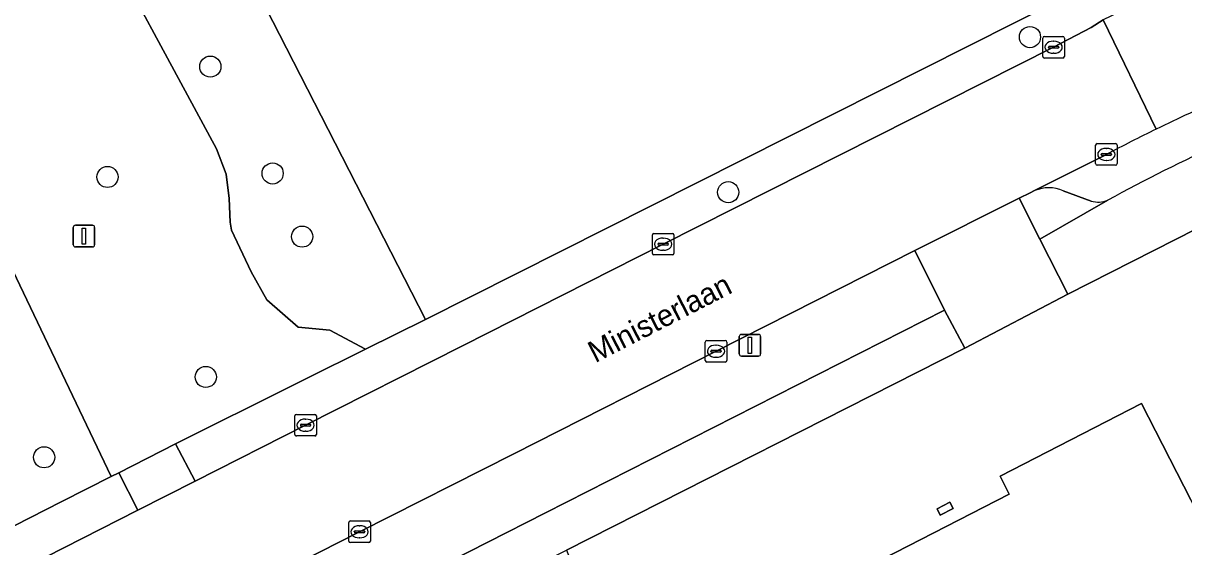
# Model space of a CAD drawing. Extents: x 162722 to 165104, y 384719 to 386284.
# Drawn here: x 163852.8 to 163906.4, y 384926.5 to 384950.7 of the extents above; entities that cross this region are included whole.
import ezdxf

# ---------------------------------------------------------------- set-up
doc = ezdxf.new("R2010")
doc.units = 0
for name, color, linetype in [('IMGEO_Boom', 7, 'Continuous'), ('IMGEO_Erf', 7, 'Continuous'), ('IMGEO_Groenvoorziening', 7, 'Continuous'), ('IMGEO_Kolk', 7, 'Continuous'), ('IMGEO_Lichtmast', 7, 'Continuous'), ('IMGEO_Openbare_ruimte_label', 7, 'Continuous'), ('IMGEO_Pand', 7, 'Continuous'), ('IMGEO_Parkeervlak_open', 7, 'Continuous'), ('IMGEO_Rijbaan_lokaal_open', 7, 'Continuous'), ('IMGEO_Voetpad_open', 7, 'Continuous')]:
    doc.layers.add(name, color=color, linetype=linetype)

msp = doc.modelspace()

# ---------------------------------------------------------------- linework, layer by layer
at = {"layer": 'IMGEO_Boom'}
for centre in [(163899.332, 384950.102), (163861.418, 384948.739), (163864.298, 384943.799), (163856.659, 384943.638), (163885.374, 384942.931), (163865.663, 384940.878), (163861.207, 384934.392), (163853.728, 384930.677)]:
    msp.add_circle(centre, 0.489, dxfattribs=at)
at = {"layer": 'IMGEO_Erf'}
for points in [[(163883.755, 384994.016), (163880.721, 385000), (163880.397, 385000.638), (163874.468, 385012.289), (163872.821, 385015.517), (163871.523, 385018.049), (163838.691, 385001.291), (163859.479, 384960.25), (163871.364, 384937.05), (163900.699, 384951.83)], [(163908.032, 384941.753), (163901.088, 384938.216), (163896.314, 384935.724), (163877.898, 384926.387), (163881.885, 384916.57), (163888.859, 384920.152), (163887.26, 384923.265), (163895.458, 384927.475), (163898.374, 384928.972), (163897.95, 384929.798), (163904.488, 384933.156), (163906.772, 384928.708)]]:
    msp.add_lwpolyline(points, dxfattribs=at)
msp.add_lwpolyline([(163895.184, 384928.007), (163895.033, 384928.3), (163895.629, 384928.606), (163895.78, 384928.313)], close=True, dxfattribs=at)
at = {"layer": 'IMGEO_Groenvoorziening'}
for points in [[(163852.627, 384963.273), (163853.801, 384960.834), (163855.514, 384956.384), (163861.704, 384944.936), (163862.154, 384943.773), (163862.281, 384942.645), (163862.342, 384941.553), (163862.399, 384941.178), (163863.304, 384939.254), (163864.029, 384937.95), (163865.485, 384936.694), (163866.952, 384936.558), (163868.59, 384935.672), (163871.364, 384937.05), (163859.479, 384960.25), (163838.691, 385001.291)], [(163840.9, 384963.114), (163856.826, 384929.784), (163857.177, 384929.962), (163859.812, 384931.297), (163860.143, 384931.463), (163862.395, 384932.595), (163862.653, 384932.723), (163865.862, 384934.317), (163868.59, 384935.672), (163866.952, 384936.558), (163865.485, 384936.694), (163864.029, 384937.95), (163863.304, 384939.254), (163862.399, 384941.178), (163862.342, 384941.553), (163862.281, 384942.645), (163862.154, 384943.773), (163861.704, 384944.936), (163855.514, 384956.384), (163853.801, 384960.834), (163852.627, 384963.273)]]:
    msp.add_lwpolyline(points, dxfattribs=at)
for points in [[(163821.501, 384989.907), (163822.453, 384988.419), (163823.674, 384985.023), (163825.844, 384980.889), (163828.596, 384975.798), (163827.544, 384974.063), (163829.673, 384970.329), (163831.854, 384966.281), (163833.717, 384961.939), (163834.732, 384959.963), (163838.385, 384956.066), (163840.819, 384951.291), (163842.832, 384945.951), (163844.556, 384940.861), (163846.709, 384935.032), (163848.58, 384930.349), (163850.721, 384926.692), (163850.884, 384926.775), (163854.555, 384928.634), (163856.826, 384929.784), (163840.9, 384963.114), (163834.379, 384974.661), (163827.686, 384987.569), (163826.306, 384989.862)], [(163868.912, 384924.044), (163876.924, 384928.111), (163895.383, 384937.48), (163894.005, 384940.23), (163884.811, 384935.58), (163875.45, 384930.841), (163868.32, 384927.232), (163848.226, 384917.022), (163844.277, 384915.026), (163845.685, 384912.215)]]:
    msp.add_lwpolyline(points, close=True, dxfattribs=at)
at = {"layer": 'IMGEO_Kolk'}
for p, q in [((163900.001, 384950.133), (163900.853, 384950.133)), ((163899.926, 384949.207), (163899.926, 384950.059)), ((163900.185, 384949.627), (163900.185, 384949.639)), ((163900.623, 384949.59), (163900.225, 384949.59)), ((163900.228, 384949.676), (163900.626, 384949.676)), ((163900.414, 384949.913), (163900.439, 384949.913)), ((163900.669, 384949.639), (163900.669, 384949.627)), ((163900.927, 384950.059), (163900.927, 384949.207)), ((163900.853, 384949.133), (163900.001, 384949.133)), ((163900.437, 384949.353), (163900.412, 384949.353)), ((163902.366, 384944.251), (163902.366, 384945.103)), ((163902.441, 384945.177), (163903.293, 384945.177)), ((163902.668, 384944.72), (163903.066, 384944.72)), ((163902.854, 384944.957), (163902.879, 384944.957)), ((163903.367, 384945.103), (163903.367, 384944.251)), ((163903.293, 384944.177), (163902.441, 384944.177)), ((163902.625, 384944.671), (163902.625, 384944.683)), ((163903.063, 384944.634), (163902.665, 384944.634)), ((163902.877, 384944.397), (163902.852, 384944.397)), ((163903.109, 384944.683), (163903.109, 384944.671)), ((163881.864, 384940.103), (163881.864, 384940.955)), ((163881.939, 384941.029), (163882.791, 384941.029)), ((163882.865, 384940.955), (163882.865, 384940.103)), ((163882.123, 384940.523), (163882.123, 384940.535)), ((163882.561, 384940.486), (163882.163, 384940.486)), ((163882.166, 384940.572), (163882.564, 384940.572)), ((163882.352, 384940.809), (163882.377, 384940.809)), ((163882.607, 384940.535), (163882.607, 384940.523)), ((163882.791, 384940.029), (163881.939, 384940.029)), ((163882.375, 384940.249), (163882.35, 384940.249)), ((163884.31, 384935.154), (163884.31, 384936.006)), ((163884.385, 384936.08), (163885.237, 384936.08)), ((163884.569, 384935.574), (163884.569, 384935.586)), ((163884.612, 384935.623), (163885.01, 384935.623)), ((163884.798, 384935.86), (163884.823, 384935.86)), ((163885.053, 384935.586), (163885.053, 384935.574)), ((163885.311, 384936.006), (163885.311, 384935.154)), ((163885.237, 384935.08), (163884.385, 384935.08)), ((163885.007, 384935.537), (163884.609, 384935.537)), ((163884.821, 384935.3), (163884.796, 384935.3)), ((163865.322, 384931.735), (163865.322, 384932.587)), ((163865.397, 384932.661), (163866.249, 384932.661)), ((163865.81, 384932.441), (163865.835, 384932.441)), ((163866.323, 384932.587), (163866.323, 384931.735)), ((163865.581, 384932.155), (163865.581, 384932.167)), ((163866.019, 384932.118), (163865.621, 384932.118)), ((163865.624, 384932.204), (163866.022, 384932.204)), ((163865.833, 384931.881), (163865.808, 384931.881)), ((163866.065, 384932.167), (163866.065, 384932.155)), ((163866.249, 384931.661), (163865.397, 384931.661)), ((163867.819, 384926.806), (163867.819, 384927.658)), ((163867.894, 384927.732), (163868.746, 384927.732)), ((163868.82, 384927.658), (163868.82, 384926.806)), ((163868.078, 384927.226), (163868.078, 384927.238)), ((163868.516, 384927.189), (163868.118, 384927.189)), ((163868.121, 384927.275), (163868.519, 384927.275)), ((163868.307, 384927.512), (163868.332, 384927.512)), ((163868.562, 384927.238), (163868.562, 384927.226)), ((163868.746, 384926.732), (163867.894, 384926.732)), ((163868.33, 384926.952), (163868.305, 384926.952))]:
    msp.add_line(p, q, dxfattribs=at)
for points in [[(163900.001, 384950.133), (163900.853, 384950.133)], [(163899.926, 384949.207), (163899.926, 384950.059)], [(163900.927, 384950.059), (163900.927, 384949.207)], [(163900.853, 384949.133), (163900.001, 384949.133)], [(163902.366, 384944.251), (163902.366, 384945.103)], [(163902.441, 384945.177), (163903.293, 384945.177)], [(163903.367, 384945.103), (163903.367, 384944.251)], [(163903.293, 384944.177), (163902.441, 384944.177)], [(163881.864, 384940.103), (163881.864, 384940.955)], [(163881.939, 384941.029), (163882.791, 384941.029)], [(163882.865, 384940.955), (163882.865, 384940.103)], [(163882.791, 384940.029), (163881.939, 384940.029)], [(163884.31, 384935.154), (163884.31, 384936.006)], [(163884.385, 384936.08), (163885.237, 384936.08)], [(163885.311, 384936.006), (163885.311, 384935.154)], [(163885.237, 384935.08), (163884.385, 384935.08)], [(163865.322, 384931.735), (163865.322, 384932.587)], [(163865.397, 384932.661), (163866.249, 384932.661)], [(163866.323, 384932.587), (163866.323, 384931.735)], [(163866.249, 384931.661), (163865.397, 384931.661)], [(163867.819, 384926.806), (163867.819, 384927.658)], [(163867.894, 384927.732), (163868.746, 384927.732)], [(163868.82, 384927.658), (163868.82, 384926.806)], [(163868.746, 384926.732), (163867.894, 384926.732)]]:
    msp.add_lwpolyline(points, dxfattribs=at)
for centre, radius, start, end in [((163900.003, 384950.057), 0.0765, 91.552, 178.448), ((163900.003, 384950.057), 0.0765, 91.552, 178.448), ((163900.851, 384950.057), 0.0765, 1.552, 88.448), ((163900.851, 384950.057), 0.0765, 1.552, 88.448), ((163900.225, 384949.636), 0.0403, 85.8775, 175.7526), ((163900.222, 384949.626), 0.0366, 178.938, 274.7102), ((163900.626, 384949.633), 0.043, 264.8664, 352.4533), ((163900.63, 384949.638), 0.0386, 1.7309, 96.639), ((163900.003, 384949.209), 0.0765, 181.552, 268.448), ((163900.003, 384949.209), 0.0765, 181.552, 268.448), ((163900.851, 384949.209), 0.0765, 271.552, 358.448), ((163900.851, 384949.209), 0.0765, 271.552, 358.448), ((163902.443, 384945.101), 0.0765, 91.552, 178.448), ((163902.443, 384945.101), 0.0765, 91.552, 178.448), ((163902.665, 384944.68), 0.0403, 85.8775, 175.7526), ((163903.07, 384944.682), 0.0386, 1.7309, 96.639), ((163903.291, 384945.101), 0.0765, 1.552, 88.448), ((163903.291, 384945.101), 0.0765, 1.552, 88.448), ((163902.443, 384944.253), 0.0765, 181.552, 268.448), ((163902.443, 384944.253), 0.0765, 181.552, 268.448), ((163902.662, 384944.67), 0.0366, 178.938, 274.7102), ((163903.066, 384944.677), 0.043, 264.8664, 352.4533), ((163903.291, 384944.253), 0.0765, 271.552, 358.448), ((163903.291, 384944.253), 0.0765, 271.552, 358.448), ((163881.941, 384940.953), 0.0765, 91.552, 178.448), ((163881.941, 384940.953), 0.0765, 91.552, 178.448), ((163882.789, 384940.953), 0.0765, 1.552, 88.448), ((163882.789, 384940.953), 0.0765, 1.552, 88.448), ((163882.163, 384940.532), 0.0403, 85.8775, 175.7526), ((163882.16, 384940.522), 0.0366, 178.938, 274.7102), ((163882.564, 384940.529), 0.043, 264.8664, 352.4533), ((163882.568, 384940.534), 0.0386, 1.7309, 96.639), ((163881.941, 384940.105), 0.0765, 181.552, 268.448), ((163881.941, 384940.105), 0.0765, 181.552, 268.448), ((163882.789, 384940.105), 0.0765, 271.552, 358.448), ((163882.789, 384940.105), 0.0765, 271.552, 358.448), ((163884.387, 384936.004), 0.0765, 91.552, 178.448), ((163884.387, 384936.004), 0.0765, 91.552, 178.448), ((163884.609, 384935.583), 0.0403, 85.8775, 175.7526), ((163885.014, 384935.585), 0.0386, 1.7309, 96.639), ((163885.235, 384936.004), 0.0765, 1.552, 88.448), ((163885.235, 384936.004), 0.0765, 1.552, 88.448), ((163884.387, 384935.156), 0.0765, 181.552, 268.448), ((163884.387, 384935.156), 0.0765, 181.552, 268.448), ((163884.606, 384935.573), 0.0366, 178.938, 274.7102), ((163885.01, 384935.58), 0.043, 264.8664, 352.4533), ((163885.235, 384935.156), 0.0765, 271.552, 358.448), ((163885.235, 384935.156), 0.0765, 271.552, 358.448), ((163865.399, 384932.585), 0.0765, 91.552, 178.448), ((163865.399, 384932.585), 0.0765, 91.552, 178.448), ((163866.247, 384932.585), 0.0765, 1.552, 88.448), ((163866.247, 384932.585), 0.0765, 1.552, 88.448), ((163865.621, 384932.164), 0.0403, 85.8775, 175.7526), ((163865.618, 384932.154), 0.0366, 178.938, 274.7102), ((163866.022, 384932.161), 0.043, 264.8664, 352.4533), ((163866.026, 384932.166), 0.0386, 1.7309, 96.639), ((163865.399, 384931.737), 0.0765, 181.552, 268.448), ((163865.399, 384931.737), 0.0765, 181.552, 268.448), ((163866.247, 384931.737), 0.0765, 271.552, 358.448), ((163866.247, 384931.737), 0.0765, 271.552, 358.448), ((163867.896, 384927.656), 0.0765, 91.552, 178.448), ((163867.896, 384927.656), 0.0765, 91.552, 178.448), ((163868.744, 384927.656), 0.0765, 1.552, 88.448), ((163868.744, 384927.656), 0.0765, 1.552, 88.448), ((163868.118, 384927.235), 0.0403, 85.8775, 175.7526), ((163868.115, 384927.225), 0.0366, 178.938, 274.7102), ((163868.519, 384927.232), 0.043, 264.8664, 352.4533), ((163868.523, 384927.237), 0.0386, 1.7309, 96.639), ((163867.896, 384926.808), 0.0765, 181.552, 268.448), ((163867.896, 384926.808), 0.0765, 181.552, 268.448), ((163868.744, 384926.808), 0.0765, 271.552, 358.448), ((163868.744, 384926.808), 0.0765, 271.552, 358.448)]:
    msp.add_arc(centre, radius, start, end, dxfattribs=at)
for centre, major_axis, ratio, start_param, end_param in [((163900.413, 384949.633), (-0.387, 0.002), 0.722429, 4.712389, 7.853982), ((163900.438, 384949.633), (-0.39, 0.002), 0.717154, 1.570796, 4.712389), ((163902.853, 384944.677), (-0.387, 0.002), 0.722429, 4.712389, 7.853982), ((163902.878, 384944.677), (-0.39, 0.002), 0.717154, 1.570796, 4.712389), ((163882.351, 384940.529), (-0.387, 0.002), 0.722429, 4.712389, 7.853982), ((163882.376, 384940.529), (-0.39, 0.002), 0.717154, 1.570796, 4.712389), ((163884.797, 384935.58), (-0.387, 0.002), 0.722429, 4.712389, 7.853982), ((163884.822, 384935.58), (-0.39, 0.002), 0.717154, 1.570796, 4.712389), ((163865.809, 384932.161), (-0.387, 0.002), 0.722429, 4.712389, 7.853982), ((163865.834, 384932.161), (-0.39, 0.002), 0.717154, 1.570796, 4.712389), ((163868.306, 384927.232), (-0.387, 0.002), 0.722429, 4.712389, 7.853982), ((163868.331, 384927.232), (-0.39, 0.002), 0.717154, 1.570796, 4.712389)]:
    msp.add_ellipse(centre, major_axis=major_axis, ratio=ratio, start_param=start_param, end_param=end_param, dxfattribs=at)
at = {"layer": 'IMGEO_Lichtmast'}
for p, q in [((163855.075, 384940.5), (163855.075, 384941.3)), ((163855.075, 384941.3), (163855.075, 384940.5)), ((163855.175, 384941.4), (163855.965, 384941.4)), ((163855.965, 384941.4), (163855.175, 384941.4)), ((163856.065, 384941.3), (163856.065, 384940.5)), ((163856.065, 384940.5), (163856.065, 384941.3)), ((163855.965, 384940.4), (163855.175, 384940.4)), ((163855.175, 384940.4), (163855.965, 384940.4)), ((163885.884, 384935.455), (163885.884, 384936.255)), ((163885.884, 384936.255), (163885.884, 384935.455)), ((163885.984, 384936.355), (163886.774, 384936.355)), ((163886.774, 384936.355), (163885.984, 384936.355)), ((163886.874, 384936.255), (163886.874, 384935.455)), ((163886.874, 384935.455), (163886.874, 384936.255)), ((163886.774, 384935.355), (163885.984, 384935.355)), ((163885.984, 384935.355), (163886.774, 384935.355))]:
    msp.add_line(p, q, dxfattribs=at)
for points in [[(163855.495, 384941.275), (163855.645, 384941.275), (163855.645, 384940.525), (163855.495, 384940.525), (163855.495, 384941.275)], [(163886.304, 384936.23), (163886.454, 384936.23), (163886.454, 384935.48), (163886.304, 384935.48), (163886.304, 384936.23)]]:
    msp.add_lwpolyline(points, dxfattribs=at)
for centre, start, end in [((163855.175, 384941.3), 90, 180), ((163855.175, 384941.3), 90, 180), ((163855.965, 384941.3), 0, 90), ((163855.965, 384941.3), 360, 90), ((163855.175, 384940.5), 180, 270), ((163855.175, 384940.5), 180, 270), ((163855.965, 384940.5), 270, 0), ((163855.965, 384940.5), 270, 0), ((163885.984, 384936.255), 90, 180), ((163885.984, 384936.255), 90, 180), ((163886.774, 384936.255), 0, 90), ((163886.774, 384936.255), 360, 90), ((163885.984, 384935.455), 180, 270), ((163885.984, 384935.455), 180, 270), ((163886.774, 384935.455), 270, 0), ((163886.774, 384935.455), 270, 0)]:
    msp.add_arc(centre, 0.1, start, end, dxfattribs=at)
at = {"layer": 'IMGEO_Pand'}
for points in [[(163891.844, 384897.178), (163898.818, 384900.759), (163891.618, 384914.779), (163897.847, 384917.978), (163901.302, 384911.25), (163909.102, 384915.257), (163905.67, 384921.938), (163909.293, 384923.799), (163906.772, 384928.708), (163904.488, 384933.156), (163897.95, 384929.798), (163898.374, 384928.972), (163895.458, 384927.475), (163887.26, 384923.265), (163888.859, 384920.152), (163881.885, 384916.57)], [(163895.033, 384928.3), (163895.184, 384928.007), (163895.78, 384928.313), (163895.629, 384928.606)]]:
    msp.add_lwpolyline(points, close=True, dxfattribs=at)
at = {"layer": 'IMGEO_Parkeervlak_open'}
for points in [[(163900.699, 384951.83), (163871.364, 384937.05), (163868.59, 384935.672), (163865.862, 384934.317), (163862.653, 384932.723), (163862.395, 384932.595), (163860.143, 384931.463), (163859.812, 384931.297), (163860.722, 384929.573), (163865.823, 384932.161), (163873.077, 384935.831), (163882.365, 384940.529)], [(163882.365, 384940.529), (163900.427, 384949.633), (163902.168, 384950.54), (163902.719, 384950.896)], [(163902.867, 384944.677), (163899.547, 384943.004)], [(163900.874, 384943), (163902.166, 384942.522)]]:
    msp.add_lwpolyline(points, dxfattribs=at)
msp.add_lwpolyline([(163858.06, 384928.229), (163857.177, 384929.962), (163856.826, 384929.784), (163854.555, 384928.634), (163850.884, 384926.775), (163850.721, 384926.692), (163850.092, 384926.374), (163844.43, 384923.507), (163834.666, 384918.562), (163835.53, 384916.828), (163847.803, 384923.025)], close=True, dxfattribs=at)
for centre, radius, start, end in [((163938.782, 384877.001), 76.612, 113.47653, 116.01721), ((163939.408, 384875.578), 78.166, 115.97155, 117.87066), ((163938.457, 384877.857), 73.819, 114.18669, 118.76979), ((163900.206, 384941.439), 1.698, 66.8257, 112.8289), ((163902.491, 384943.56), 1.088, 252.6214, 293.6883)]:
    msp.add_arc(centre, radius, start, end, dxfattribs=at)
at = {"layer": 'IMGEO_Rijbaan_lokaal_open'}
for points in [[(163912.409, 384955.562), (163902.719, 384950.896), (163905.177, 384945.85)], [(163905.177, 384945.85), (163902.719, 384950.896), (163902.168, 384950.54), (163900.427, 384949.633), (163882.365, 384940.529), (163873.077, 384935.831), (163865.823, 384932.161), (163860.722, 384929.573), (163858.06, 384928.229), (163847.803, 384923.025), (163835.53, 384916.828), (163830.317, 384914.202), (163827.86, 384912.942), (163826.397, 384912.222), (163820.324, 384909.131), (163816.539, 384907.204), (163808.313, 384902.998), (163803.402, 384900.516), (163795.08, 384896.282), (163779.841, 384888.62)], [(163848.226, 384917.022), (163868.32, 384927.232), (163875.45, 384930.841), (163884.811, 384935.58), (163894.005, 384940.23), (163898.835, 384942.654), (163899.34, 384942.899), (163899.547, 384943.004), (163902.867, 384944.677)]]:
    msp.add_lwpolyline(points, dxfattribs=at)
for centre, radius, start, end in [((163938.782, 384877.001), 76.612, 113.47653, 116.01721), ((163939.408, 384875.578), 78.166, 115.97155, 117.87066)]:
    msp.add_arc(centre, radius, start, end, dxfattribs=at)
at = {"layer": 'IMGEO_Voetpad_open'}
for points in [[(163895.383, 384937.48), (163896.314, 384935.724), (163901.088, 384938.216), (163899.79, 384940.765), (163898.835, 384942.654), (163894.005, 384940.23)], [(163868.912, 384924.044), (163845.685, 384912.215), (163846.504, 384910.599), (163858.338, 384916.535), (163867.928, 384921.346), (163869.718, 384922.244), (163870.537, 384922.655), (163877.898, 384926.387), (163896.314, 384935.724), (163895.383, 384937.48), (163876.924, 384928.111)], [(163860.722, 384929.573), (163859.812, 384931.297), (163857.177, 384929.962), (163858.06, 384928.229)]]:
    msp.add_lwpolyline(points, close=True, dxfattribs=at)
for points in [[(163899.547, 384943.004), (163899.34, 384942.899), (163898.835, 384942.654), (163899.79, 384940.765), (163902.928, 384942.564)], [(163902.166, 384942.522), (163900.874, 384943)], [(163902.928, 384942.564), (163899.79, 384940.765), (163901.088, 384938.216), (163908.032, 384941.753), (163908.065, 384941.624)]]:
    msp.add_lwpolyline(points, dxfattribs=at)
for centre, radius, start, end in [((163938.457, 384877.857), 73.819, 114.18669, 118.76979), ((163900.206, 384941.439), 1.698, 66.8257, 112.8289), ((163902.491, 384943.56), 1.088, 252.6214, 293.6883)]:
    msp.add_arc(centre, radius, start, end, dxfattribs=at)

# ---------------------------------------------------------------- texts
at = {"layer": 'IMGEO_Openbare_ruimte_label'}
msp.add_text('Ministerlaan', height=1, rotation=27.1797, dxfattribs=at).set_placement((163879.222, 384935.02))

doc.saveas('drawing.dxf')
